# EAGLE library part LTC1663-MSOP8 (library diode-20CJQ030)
Linear's LTC1663 10-Bit Rail-to-Rail Micropower DAC with 2-Wire Interface Description: The LTC®1663 is a 10-bit voltage output DAC with true buffered rail-to-rail output voltage capability. It operates from a single supply with a range of 2.7V to 5.5V. The reference for the DAC is selectable between the supply voltage or an internal bandgap reference. Selecting the internal bandgap reference will set the full-scale output voltage range to 2.5V. Selecting the supply as the reference sets the output voltage range to the supply voltage. The part features a simple 2-wire serial interface compatible with SMBus and I2C that allows communication between many devices. The internal data registers are double buffered to allow for simultaneous update of several devices at once. The DAC can be put in low current power-down mode for use in power conscious systems. Power-on reset ensures the DAC output is at 0V when power is initially applied, and all internal registers are cleared. Features: Micropower 10-Bit DAC in SOT-23 Low Operating Current: 60mA Ultralow Power Shutdown Mode: 10mA 2-Wire Serial Interface Compatible with SMBus and I2CTM Single 2.7V to 5.5V Operation Selectable Internal Reference or Ratiometric to VCC Buffered True Rail-to-Rail Voltage Output Maximum DNL Error: 0.75LSB Power-On Reset 8 User Selectable Addresses (MSOP Package) 0.6V VIL and 1.4V VIH for SDA and SCL Applications: Small 5-Lead SOT-23 and 8-Lead MSOP Packages Digital Calibration Offset/Gain Adjustment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
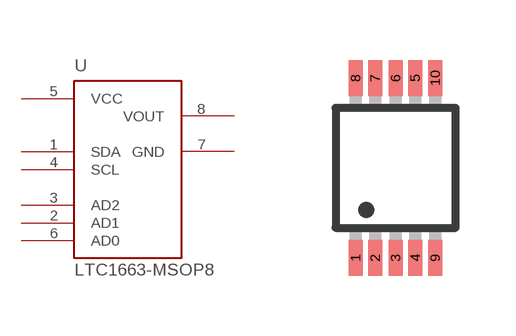
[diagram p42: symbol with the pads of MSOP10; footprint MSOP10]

Designator prefix U

## LTC1663-MSOP8  [MSOP10]
1  SDA
2  AD1  in
3  AD2  in
4  SCL
5  VCC  pwr
6  AD0  in
7  GND  pwr
8  VOUT  sup

## Footprint MSOP10 (pad centres in mm)
MSOP10
smd 0.35 x 0.9: 1 -1,-2.25; 2 -0.51,-2.25; 3 0,-2.25; 4 0.49,-2.25; 5 0.49,2.25; 6 0,2.25; 7 -0.51,2.25; 8 -1,2.25; 9 0.99,-2.25; 10 0.99,2.25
